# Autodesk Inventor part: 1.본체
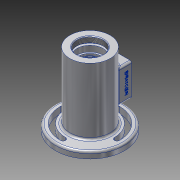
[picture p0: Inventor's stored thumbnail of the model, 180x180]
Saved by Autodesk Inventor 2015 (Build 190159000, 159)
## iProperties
Created: 2017-05
Part Number: 1.본체
Material: 알루미늄 6061
Document SubType Name: Modeling
Designer: user
Density: 2.7 g/cm^3
Appearance: 알루미늄 - 평지
Author: user
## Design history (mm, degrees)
sketch "스케치1"
  geometry: C1 r 31 at (0, 0); 1 further point
  constraints: 1 centre point, 1 coincident
  dimensions: "d0" = 62 diameter of C1
extrude "돌출1" new body sketch "스케치1" distance "d1" = 102; taper "d2" = 0 deg
sketch "스케치2"
  geometry: C1 r 53 at (0, 0); 1 further point
  constraints: 1 centre point, 1 coincident
  dimensions: "d3" = 106 diameter of C1
extrude "돌출2" join sketch "스케치2" distance "d4" = 10; taper "d5" = 0 deg
sketch "스케치3"
  geometry: C1 r 31 at (0, 0); 1 further point
  constraints: 1 centre point, 1 coincident
  dimensions: "d6" = 62 diameter of C1
extrude "돌출3" join sketch "스케치3" distance "d7" = 3; taper "d8" = 0 deg
hole "구멍1" diameter "d11" = 40.376; stored, may be unused: countersink angle "d15" = 90 deg, drill point angle "d17" = 0 deg; dims "d12" = 9, "d13" = 4, "d14" = 2, "d16" = 9, "d18" = 10, "d19" = 10
node "작업 평면1"
sketch "스케치4"
  geometry: L1 (-20, -31)-(20, -31); L2 (20, -31)-(20, -81); L3 (20, -81)-(-20, -81); L4 (-20, -81)-(-20, -31); L5 (-20, -31)-(20, -81); L6 (20, -31)-(-20, -81); L7 (-31, 0)-(31, 0) reference; L8 (-31, -102)-(31, -102) reference; L9 (-31, 0)-(31, 0) reference; 2 further points
  constraints: 12 end point, 2 midpoint, 2 parallel, 1 horizontal, 1 perpendicular
  dimensions: "d21" = 56 distance from line of L7 point (0, -56); "d22" = 50 distance of L3.end L1.start; "d23" = 40 distance of L2.end L3.end; "d24" = 31 horizontal distance of L7.end point (0, -56)
extrude "돌출4" join sketch "스케치4" stored distance "d25" = 3; taper "d26" = 0 deg
sketch "스케치5"
  geometry: L1 (-31, 0)-(31, 0) reference; L2 (-31, -115)-(31, -115) reference; L3 (0, -9)-(0, -115); L4 (20.188, -9)-(-20.188, -9) reference; L5 (0, -9)-(24, -9); L6 (24, -9)-(24, -12); L7 (24, -12)-(20, -12); L8 (20, -12)-(20, -21); L9 (20, -21)-(17.5, -21); L10 (17.5, -21)-(17.5, -24.25); L11 (17.5, -24.25)-(18.5, -24.25); L12 (18.5, -26)-(17.5, -26); L13 (17.5, -26)-(17.5, -37); L14 (17.5, -37)-(26, -37); L15 (26, -37)-(26, -75); L16 (26, -75)-(17.5, -75); L17 (17.5, -75)-(17.5, -86); L18 (17.5, -86)-(16.5, -86); L19 (16.5, -86)-(16.5, -91); L20 (16.5, -91)-(10, -91); L21 (10, -91)-(10, -93.7); L22 (10, -93.7)-(12.5, -93.7); L23 (22, -115)-(0, -115); L24 (18.5, -24.25)-(18.5, -26); L25 (12.5, -93.7)-(12.5, -100.3); L26 (12.5, -100.3)-(12.904, -101); L27 (12.904, -101)-(16, -101); L28 (16, -101)-(22, -115); 1 further point
  constraints: 50 end point, 15 perpendicular, 3 collinear, 3 vertical, 2 midpoint, 2 point on line, 1 horizontal
  dimensions: "d27" = 48 diameter of L6 L3; "d28" = 3 distance of L5.end L6.end; "d29" = 40 diameter of L8 L3; "d30" = 21 distance from line of L1 L9.end; "d31" = 35 diameter of L10 L3; "d34" = 37 diameter of L24 L3; "d35" = 1.75 distance of L11.end L12.start; "d36" = 26 distance between parallel lines of L1 L12; "d37" = 38 distance of L14.end L15.end; "d38" = 52 diameter of L15 L3; "d39" = 33 diameter of L19 L3; "d40" = 20 diameter of L21 L3; "d42" = 2.7 distance of L20.end L21.end; "d43" = 25 diameter of L25 L3; "d44" = 7.3 distance from line of L26.end L22; "d45" = 0.7 vertical distance of L26.end L25.end; "d46" = 30 deg angle of L25 L26; "d47" = 32 diameter of L27.end L3; "d48" = 44 diameter of L23.start L3; "d49" = 11 distance of L16.end L17.end; "d50" = 60 distance between parallel lines of L18 L12; "d51" = 14 distance between parallel lines of L2 L27
revolve "회전1" sketch "스케치5" stored, may be unused: angle "d52" = 90 deg
sketch "스케치7"
  geometry: L1 (11, 40)-(-11, 40); L2 (-11, 40)-(-11, 72); L3 (-11, 72)-(11, 72); L4 (11, 72)-(11, 40); L5 (11, 40)-(-11, 72); L6 (-11, 40)-(11, 72); L7 (20, 31)-(-20, 31) reference; L8 (-20, 31)-(-20, 81) reference; 2 further points
  constraints: 12 end point, 2 midpoint, 2 parallel, 1 horizontal, 1 perpendicular
  dimensions: "d53" = 32 distance of L1.end L2.end; "d54" = 22 distance of L1.start L1.end; "d55" = 9 distance between parallel lines of L7 L1; "d56" = 9 distance between parallel lines of L8 L2
extrude "돌출5" cut sketch "스케치7" stored distance "d57" = 3; taper "d58" = 0 deg
sketch "스케치8"
  geometry: L1 (20, 31)-(-20, 31) reference; L2 (-20, 31)-(-20, 81) reference; 2 further points
  dimensions: "d59" = 4.5 distance from line of L1 point (-15.5, 35.5); "d60" = 4.5 distance from line of L2 point (-15.5, 35.5)
hole "구멍2" sketch "스케치8" at (-15.5, 35.5) diameter "d61" = 2.459; stored, may be unused: countersink angle "d65" = 90 deg, drill point angle "d67" = 118 deg; dims "d62" = 6, "d63" = 4, "d64" = 2, "d66" = 8
sketch "스케치9"
  geometry: L1 (0, 0)-(-53, 0); L2 (0, 0)-(0, 53); L3 (29.345, 29.345)-(-29.345, -29.345); A1 r 41.5 centre (0, 0) between (0, 41.5) and (29.345, 29.345); A2 r 41.5 centre (0, 0) between (0, 41.5) and (-41.5, 0); A3 r 45.5 centre (0, 0) between (0, 45.5) and (-45.5, 0); A4 r 37.5 centre (0, 0) between (0, 37.5) and (-37.5, 0); A5 r 4 centre (0, 41.5) between (0, 37.5) and (0, 45.5); A6 r 4 centre (-41.5, 0) between (-45.5, 0) and (-37.5, 0); A7 r 53 centre (0, 0) between (-53, 0) and (0, 53) reference; A8 r 4 centre (41.5, 0) between (45.5, 0) and (37.5, 0); A9 r 45.5 centre (0, 0) between (0, -45.5) and (45.5, 0); A10 r 37.5 centre (0, 0) between (0, -37.5) and (37.5, 0); A11 r 4 centre (0, -41.5) between (0, -37.5) and (0, -45.5); 2 further points
  constraints: 23 point on circle, 10 centre point, 6 end point, 6 symmetric about line, 4 tangent, 3 coincident, 2 point on line, 1 concentric, 1 horizontal, 1 midpoint, 1 perpendicular, 4 other
  dimensions: "d74" = 83 diameter of A1; "d75" = 4 radius of A5; "d76" = 45 deg angle of L2 L3
extrude "돌출6" cut sketch "스케치9" stored distance "d77" = 3; taper "d78" = 0 deg
node "작업 평면2"
sketch "스케치10"
  geometry: L1 (50, 0)-(0, 0) reference; L2 (-31, -75)-(-31, -13) reference; 2 further points
  constraints: 1 other
  dimensions: "d80" = 8 distance from line of L1 point (25, -8); "d81" = 56 distance from line of L2 point (25, -8)
feature "엠보싱1" sketch "스케치10" dims "d82" = 0.5, "d83" = 0
chamfer "모따기1" distance "d84" = 1; stored, may be unused: second distance "d85" = 2, angle "d86" = 45 deg
fillet "모깎기1" dims "d87" = 3
chamfer "모따기2" distance "d89" = 1; stored, may be unused: second distance "d90" = 2, angle "d91" = 45 deg
fillet "모깎기4" dims "d93" = 3
fillet "모깎기5" dims "d94" = 0.3
fillet "모깎기6" dims "d95" = 3
chamfer "모따기3" distance "d96" = 1; stored, may be unused: second distance "d97" = 2, angle "d98" = 45 deg
fillet "모깎기7" dims "d99" = 3
fillet "모깎기8" dims "d100" = 3
node "솔리드1"
pattern_linear "직사각형 패턴1" dims "d70" = 41, "d73" = 31
node "투영된 루프1"
other parameters: "d20" = 44, "d79" = 5
